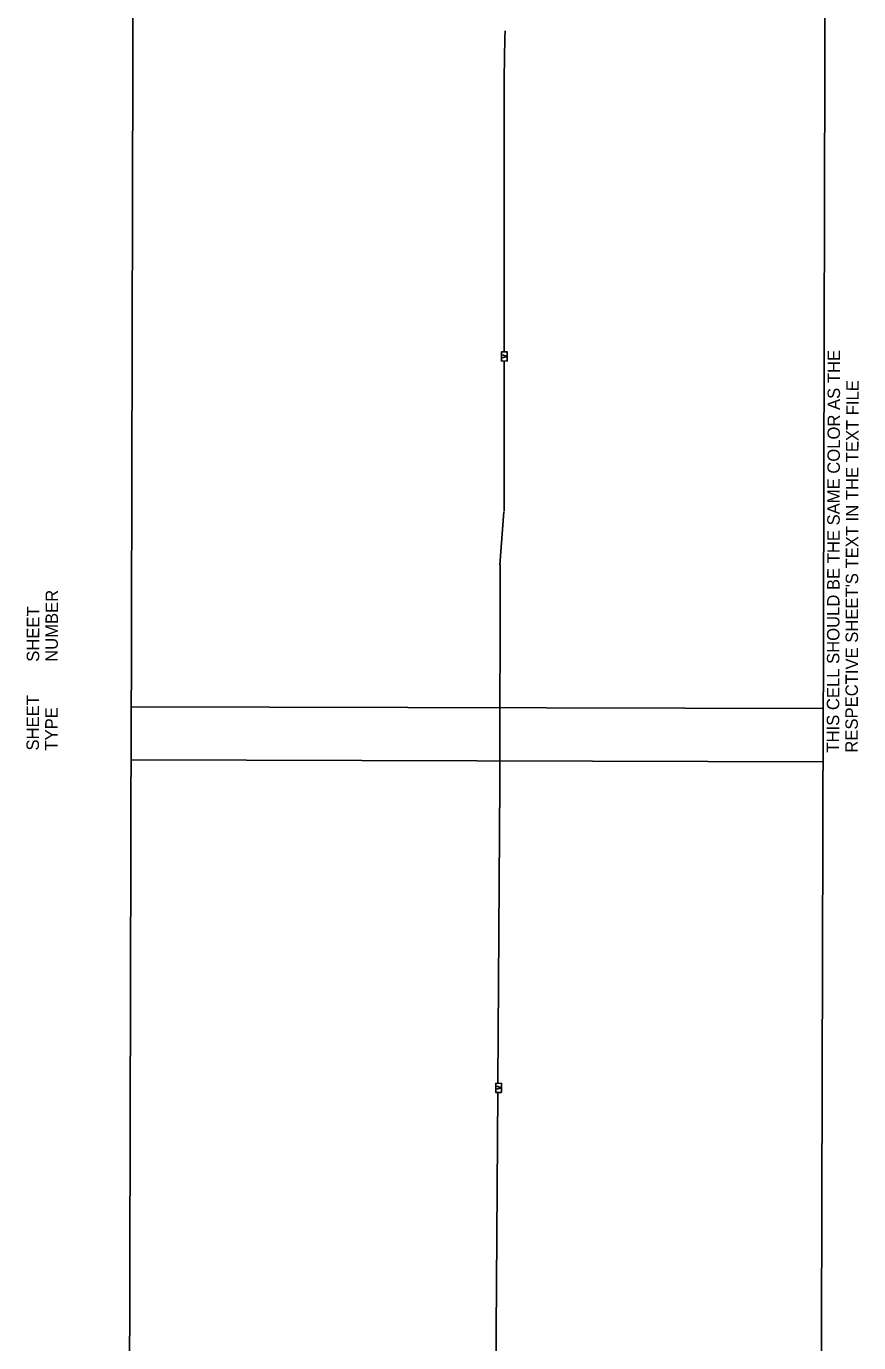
# Model space of a CAD drawing. Extents: x 601462 to 605493, y 331960 to 402715.
# Drawn here: x 602639 to 603811, y 373327 to 375180 of the extents above; entities that cross this region are included whole.
import ezdxf

# ---------------------------------------------------------------- set-up
doc = ezdxf.new("R2010")
doc.units = 0
for name, color, linetype in [('P_FTMS', 7, 'Continuous'), ('P_FTMSConduit', 7, 'Continuous'), ('P_MISC_TXT_1A (Construction)', 7, 'Continuous'), ('P_MISC_TXT_1B (Construction)', 7, 'Continuous')]:
    doc.layers.add(name, color=color, linetype=linetype)

# ---------------------------------------------------------------- blocks, each defined once
blk = doc.blocks.new('FTMS_FCV')
at = {"layer": 'P_FTMS'}
blk.add_line((13, 16), (1, -22), dxfattribs=at)
blk.add_lwpolyline([(39, 24), (-39, 24), (-39, -24), (39, -24)], close=True, dxfattribs=at)
blk.add_lwpolyline([(-12, 16), (1, -22)], dxfattribs=at)

msp = doc.modelspace()

# ---------------------------------------------------------------- linework, layer by layer
at = {"layer": 'P_FTMSConduit'}
for p, q in [((603311.8, 374721.8), (603312, 375097.6)), ((603311.7, 374497.3), (603311.8, 374708.9)), ((603311.6, 374496.7), (603305.6, 374422))]:
    msp.add_line(p, q, dxfattribs=at)
for points in [[(603303, 373691.8), (603305.8, 374115.5), (603306, 374422.5)], [(603299.2, 373140.9), (603302.7, 373679)]]:
    msp.add_lwpolyline(points, dxfattribs=at)
msp.add_arc((606297, 375095.8), 2985, 178.5029, 179.9657, dxfattribs=at)
at = {"layer": 'P_MISC_TXT_1A (Construction)'}
msp.add_lwpolyline([(603757.3, 372644.6), (603761.3, 374219.6), (602786.3, 374222.1), (602782.3, 372647.1)], close=True, dxfattribs=at)
msp.add_lwpolyline([(603757.3, 372644.6), (603761.3, 374219.6), (602786.3, 374222.1), (602782.3, 372647.1)], close=True, dxfattribs=at)
at = {"layer": 'P_MISC_TXT_1B (Construction)'}
msp.add_lwpolyline([(603761.1, 374144.6), (603765.2, 375719.6), (602790.2, 375722.1), (602786.1, 374147.1)], close=True, dxfattribs=at)
msp.add_lwpolyline([(603761.1, 374144.6), (603765.2, 375719.6), (602790.2, 375722.1), (602786.1, 374147.1)], close=True, dxfattribs=at)

# ---------------------------------------------------------------- block references
at = {"layer": 'P_FTMS', "xscale": 0.16404166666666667, "yscale": 0.16404166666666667, "rotation": 88.76248754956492}
for p in [(603312.1, 374715.4), (603304.1, 373685.4)]:
    msp.add_blockref('FTMS_FCV', p, dxfattribs=at)

# ---------------------------------------------------------------- texts
at = {"layer": 'P_MISC_TXT_1B (Construction)'}
for s, p in [('THIS CELL SHOULD BE THE SAME COLOR AS THE', (603783.8, 374157.5)), ('THIS CELL SHOULD BE THE SAME COLOR AS THE', (603783.8, 374157.5)), ("RESPECTIVE SHEET'S TEXT IN THE TEXT FILE", (603810, 374157.4)), ("RESPECTIVE SHEET'S TEXT IN THE TEXT FILE", (603810, 374157.4)), ('NUMBER', (602682.9, 374285.3)), ('NUMBER', (602682.9, 374285.3)), ('SHEET', (602656.6, 374285.4)), ('SHEET', (602656.6, 374285.4)), ('SHEET', (602656.3, 374160.4)), ('SHEET', (602656.3, 374160.4)), ('TYPE', (602682.5, 374160.3)), ('TYPE', (602682.5, 374160.3))]:
    msp.add_text(s, height=17.5, rotation=89.8526, dxfattribs=at).set_placement(p)

doc.saveas('drawing.dxf')
